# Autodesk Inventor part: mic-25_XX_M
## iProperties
Shininess: 20.0
Length Units: 11269
Angle Units: 11279
Time Units: 11290
Mass Units: 11283
Length Display Precision: 2
Angle Display Precision: 2
Part Number: mic-25_XX_M
Material: Nichtrostender Stahl - 440C
Document SubType Name: Modellieren
Description: mic 25 Sensoren
Checked By: Alves
Created: 2005-08
Designer: Ohle
Manufacturer: Standard
Standards Organization: Custom
Density: 0.0
Volumn: 0.0
Area: 0.0
PropertySet Name: Model Information
Control State: 0
Master: False
Checked Out: False
Last Check In By: Kramp
Last Check In Date: 2005-08-09
BESTELLNUMMER: mic-25/XX/M
ME: ST
Title: mic Sensoren
Author: Ohle
Comments: keine Bemerkung
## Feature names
1. Grundkörper [Revolution]
2. Bohrung1 [Hole]
3. Pole [Extrusion]
4. Abrundung Pole [Fillet]
5. Verdrehsicherung [Extrusion]
